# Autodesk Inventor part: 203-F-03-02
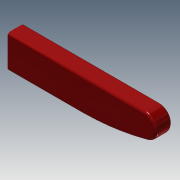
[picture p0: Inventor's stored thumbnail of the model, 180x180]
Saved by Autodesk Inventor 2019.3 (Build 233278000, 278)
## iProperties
Created: 2012-09
Part Number: 203-F-03-02
Material: Ogólny
Document SubType Name: Modeling
Designer: CADENGINEERING4
Density: 1 g/cm^3
Appearance: Czerwona
Author: CADENGINEERING4
Revision Number: ÈÎºÎ
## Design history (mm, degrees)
feature "³é¿Ç2"
node "Bryła1"
